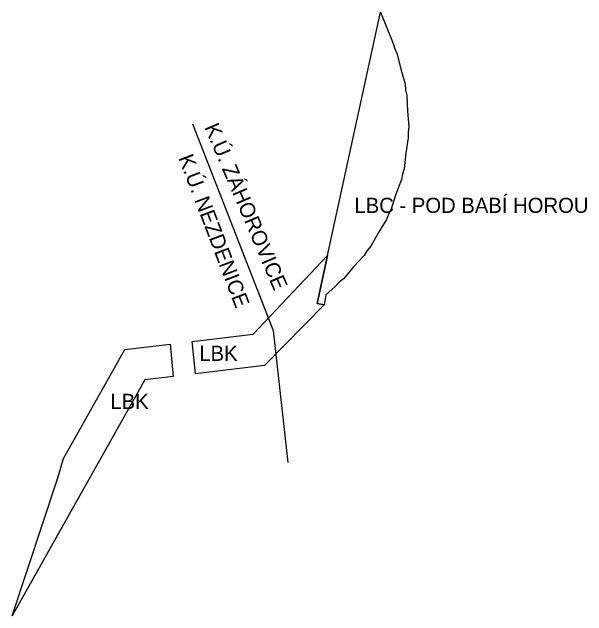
# Model space of a CAD drawing. Extents: x -521715 to -516578, y -1190280 to -1184826.
# Drawn here: x -516843.9 to -516578.1, y -1186925.1 to -1186646 of the extents above; entities that cross this region are included whole.
import ezdxf

# ---------------------------------------------------------------- set-up
doc = ezdxf.new("R2010")
doc.units = 0
for name, color, linetype in [('hr_ku_P_s', 7, 'Continuous'), ('LBC_s', 7, 'Continuous'), ('LBK_s', 7, 'Continuous')]:
    doc.layers.add(name, color=color, linetype=linetype)

msp = doc.modelspace()

# ---------------------------------------------------------------- linework, layer by layer
at = {"layer": 'hr_ku_P_s'}
msp.add_lwpolyline([(-516760.51, -1186697.7), (-516723.22, -1186793.18), (-516716.48, -1186854.2)], dxfattribs=at)
at = {"layer": 'LBC_s'}
msp.add_line((-516690.76, -1186769.34), (-516690.76, -1186769.34), dxfattribs=at)
msp.add_lwpolyline([(-516698, -1186758.42), (-516673.5, -1186645.97), (-516667.67, -1186660.53), (-516666.95, -1186663.03), (-516665.87, -1186665.4), (-516664.22, -1186672.42), (-516662.21, -1186679.36), (-516661.98, -1186681.95), (-516661.39, -1186684.48), (-516661.14, -1186691.7), (-516660.52, -1186698.89), (-516660.8, -1186701.47), (-516660.71, -1186704.07), (-516661.88, -1186711.21), (-516662.67, -1186718.38), (-516663.45, -1186720.85), (-516663.87, -1186723.42), (-516666.41, -1186730.19), (-516668.58, -1186737.06), (-516669.84, -1186739.34), (-516670.75, -1186741.78), (-516674.55, -1186747.92), (-516678.03, -1186754.24), (-516679.7, -1186756.23), (-516681.07, -1186758.44), (-516686.01, -1186763.73), (-516690.65, -1186769.25), (-516692.67, -1186770.87), (-516694.45, -1186772.77), (-516698.85, -1186776.64), (-516699.65, -1186781.32), (-516702.84, -1186780.63)], close=True, dxfattribs=at)
at = {"layer": 'LBK_s'}
for points in [[(-516760.56, -1186798.21), (-516732.46, -1186794.81), (-516698, -1186758.42), (-516702.84, -1186780.63), (-516699.65, -1186781.32), (-516727.26, -1186809.29), (-516759.06, -1186813.14)], [(-516759.06, -1186813.14), (-516760.56, -1186798.21)], [(-516769.38, -1186814.39), (-516782.48, -1186815.98), (-516843.88, -1186925.08), (-516822.77, -1186861.25), (-516820.15, -1186852.33), (-516791.83, -1186802), (-516770.83, -1186799.46)], [(-516770.83, -1186799.46), (-516769.38, -1186814.39)]]:
    msp.add_lwpolyline(points, dxfattribs=at)

# ---------------------------------------------------------------- texts
at = {"layer": 'hr_ku_P_s'}
for s, rotation, p in [('K.Ú. ZÁHOROVICE', 293.0822, (-516755.11, -1186699.16)), ('K.Ú. NEZDENICE', 290.8597, (-516767.08, -1186713.31))]:
    msp.add_text(s, height=7, rotation=rotation, dxfattribs=at).set_placement(p)
at = {"layer": 'LBK_s'}
for s, p in [('LBC - POD BABÍ HOROU', (-516685.61, -1186738.8)), ('LBK', (-516757.33, -1186807.19)), ('LBK', (-516798.44, -1186829.42))]:
    msp.add_text(s, height=7, dxfattribs=at).set_placement(p)

doc.saveas('drawing.dxf')
